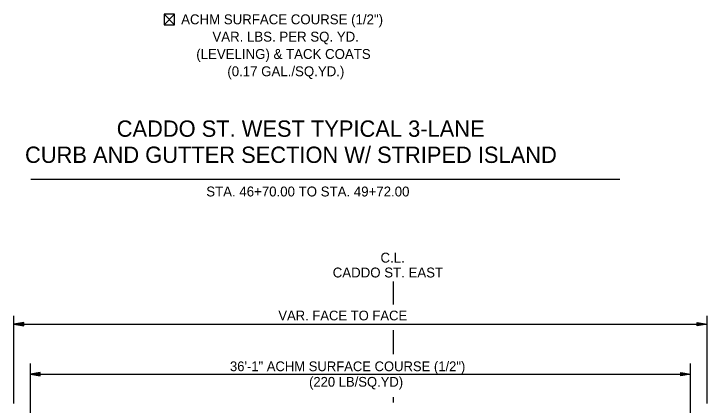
# Model space of a CAD drawing. Extents: x 1001270 to 1003428, y 1840152 to 1842912.
# Drawn here: x 1001329.63 to 1001371.63, y 1840192.06 to 1840215.77 of the extents above; entities that cross this region are included whole.
import ezdxf

# ---------------------------------------------------------------- set-up
doc = ezdxf.new("R2010")
doc.units = 0
doc.layers.add('10', color=7, linetype='Continuous')
doc.layers.add('19', color=7, linetype='Continuous')

msp = doc.modelspace()

# ---------------------------------------------------------------- linework, layer by layer
at = {"layer": '10'}
for p, q in [((1001338.732, 1840215.758), (1001339.373, 1840215.117)), ((1001339.373, 1840215.758), (1001338.732, 1840215.117)), ((1001339.113, 1840215.117), (1001339.125, 1840215.117))]:
    msp.add_line(p, q, dxfattribs=at)
msp.add_lwpolyline([(1001339.125, 1840215.117), (1001339.373, 1840215.117), (1001339.373, 1840215.758), (1001338.732, 1840215.758), (1001338.732, 1840215.117), (1001339.113, 1840215.117)], dxfattribs=at)
at = {"layer": '19'}
for p, q in [((1001330.656, 1840205.75), (1001366.349, 1840205.75)), ((1001333.678, 1840205.75), (1001363.41, 1840205.75)), ((1001352.632, 1840198.156), (1001352.632, 1840199.548)), ((1001329.632, 1840192.153), (1001329.632, 1840197.468)), ((1001371.632, 1840192.153), (1001371.632, 1840197.468)), ((1001330.232, 1840197.071), (1001329.632, 1840196.966)), ((1001329.632, 1840196.966), (1001371.632, 1840196.966)), ((1001329.632, 1840196.966), (1001330.232, 1840196.861)), ((1001330.232, 1840197.016), (1001329.792, 1840196.981)), ((1001330.232, 1840196.861), (1001330.232, 1840197.071)), ((1001371.032, 1840196.861), (1001371.032, 1840197.071)), ((1001371.032, 1840197.071), (1001371.632, 1840196.966)), ((1001371.032, 1840197.016), (1001371.472, 1840196.981)), ((1001371.632, 1840196.966), (1001371.032, 1840196.861)), ((1001329.792, 1840196.951), (1001330.232, 1840196.911)), ((1001352.632, 1840195.151), (1001352.632, 1840196.596)), ((1001371.472, 1840196.951), (1001371.032, 1840196.911)), ((1001330.632, 1840185.965), (1001330.632, 1840194.59)), ((1001370.632, 1840185.965), (1001370.632, 1840194.59)), ((1001331.232, 1840194.044), (1001330.632, 1840193.939)), ((1001331.232, 1840193.834), (1001331.232, 1840194.044)), ((1001370.032, 1840193.834), (1001370.032, 1840194.044)), ((1001370.032, 1840194.044), (1001370.632, 1840193.939)), ((1001330.632, 1840193.939), (1001331.232, 1840193.834)), ((1001330.632, 1840193.939), (1001370.632, 1840193.939)), ((1001331.232, 1840193.989), (1001330.792, 1840193.954)), ((1001330.792, 1840193.924), (1001331.232, 1840193.884)), ((1001370.032, 1840193.989), (1001370.472, 1840193.954)), ((1001370.632, 1840193.939), (1001370.032, 1840193.834)), ((1001370.472, 1840193.924), (1001370.032, 1840193.884)), ((1001352.632, 1840192.222), (1001352.632, 1840192.541))]:
    msp.add_line(p, q, dxfattribs=at)

# ---------------------------------------------------------------- texts
for s, height, rotation, p in [('ACHM SURFACE COURSE (1/2")', 0.6, 360, (1001339.767, 1840215.142)), ('VAR. LBS. PER SQ. YD.', 0.6, 360, (1001341.661, 1840214.092)), ('(LEVELING) & TACK COATS', 0.6, 360, (1001340.683, 1840213.042)), ('(0.17 GAL./SQ.YD.)', 0.6, 360, (1001342.564, 1840211.992)), ('CADDO ST. WEST TYPICAL 3-LANE ', 0.98999, 359.9954, (1001335.863, 1840208.324)), ('CURB AND GUTTER SECTION W/ STRIPED ISLAND', 0.98999, 359.9954, (1001330.308, 1840206.74)), ('STA. 46+70.00 TO STA. 49+72.00', 0.6, 359.9954, (1001341.287, 1840204.707))]:
    msp.add_text(s, height=height, rotation=rotation, dxfattribs=at).set_placement(p)
for s, height, p in [('C.L.', 0.6, (1001351.844, 1840200.697)), ('CADDO ST. EAST', 0.6, (1001348.95, 1840199.797)), ('VAR. FACE TO FACE', 0.59001, (1001345.656, 1840197.196)), ('36\'-1" ACHM SURFACE COURSE (1/2")', 0.59001, (1001342.725, 1840194.117)), ('(220 LB/SQ.YD)', 0.59001, (1001347.515, 1840193.177))]:
    msp.add_text(s, height=height, dxfattribs=at).set_placement(p)

doc.saveas('drawing.dxf')
